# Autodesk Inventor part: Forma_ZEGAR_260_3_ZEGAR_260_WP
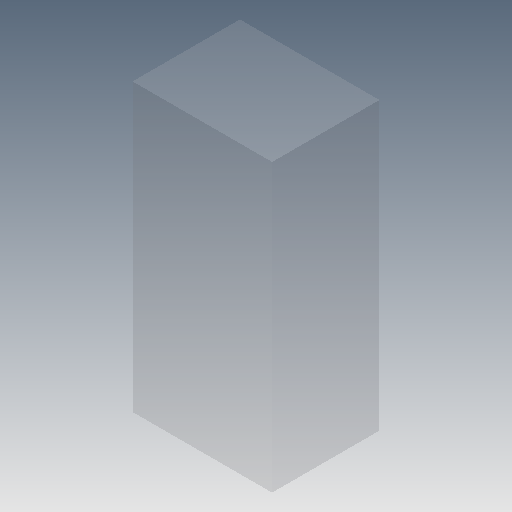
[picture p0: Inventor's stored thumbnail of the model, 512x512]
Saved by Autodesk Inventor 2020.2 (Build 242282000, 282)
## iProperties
Created: 2015-01
Part Number: Forma_ZEGAR_260_3_ZEGAR_260_WP
Material: Ogólny
Document SubType Name: Modeling
Designer: F.Stasiak
Density: 1 g/cm^3
Appearance: Domyślna
Catalog Web Link: www.expertbooks.pl
Manager: www.cadconsulting.pl
Company: Fabian Stasiak CAD Consulting
d0: -30.000 mm
d1: 39.000 mm
d2: 39.000 mm
d3: 80.000 mm
d4: 80.000 mm
d5: 60.000 mm
d6: 0.00 deg
Xmin: -39.000 mm
Ymin: -80.000 mm
Zmin: -30.000 mm
Xmax: 39.000 mm
Ymax: 80.000 mm
Zmax: 30.000 mm
Author: F.Stasiak
Subject: Zbiór ćwiczeń. Autodesk Inventor 2020. Kurs Professional
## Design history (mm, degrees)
sketch "Szkic1"
  geometry: L1 (-39, 80)-(39, 80); L2 (39, 80)-(39, -80); L3 (39, -80)-(-39, -80); L4 (-39, -80)-(-39, 80); 1 further point
  constraints: 8 end point, 2 parallel, 1 horizontal, 1 perpendicular, 1 other
  dimensions: "d1" = 39 distance from line of L4 point (0, 0) (= -Xmin); "d2" = 39 distance from line of L2 point (0, 0) (= Xmax); "d3" = 80 distance from line of L3 point (0, 0) (= -Ymin); "d4" = 80 distance from line of L1 point (0, 0) (= Ymax)
extrude "Wyciągnięcie proste1" join sketch "Szkic1" distance "d5" = 60 (= Zmax - Zmin); taper "d6" = 0 deg
node "Bryła1"
other parameters: "Xmin" = -39 [user parameter; used in 1 equation term], "Ymin" = -80 [user parameter; used in 1 equation term], "Zmin" = -30 [user parameter; used in 1 equation term], "Xmax" = 39 [user parameter; used in 1 equation term], "Ymax" = 80 [user parameter; used in 1 equation term], "Zmax" = 30 [user parameter; used in 1 equation term], "d0" = -30
